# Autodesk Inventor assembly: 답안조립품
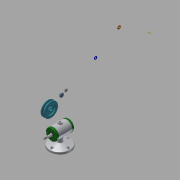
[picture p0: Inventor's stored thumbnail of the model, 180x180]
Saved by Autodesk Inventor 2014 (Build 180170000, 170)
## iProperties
Created: 2018-12
Part Number: 답안조립품
Document SubType Name: Assembly
Designer: kh
Author: kh
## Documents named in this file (15)
- C:\Users\kh\Desktop\481207V1013\답안조립품.iam
- C:\Users\kh\Desktop\481207V1013\본체.ipt
- C:\Users\kh\Desktop\481207V1013\V벨트풀리.ipt
- C:\Users\kh\Desktop\481207V1013\고무캡.ipt
- C:\Users\kh\Desktop\481207V1013\너트 M8.ipt
- 너트 M8.ipt
- C:\Users\kh\Desktop\481207V1013\뒤커버.ipt
- C:\Users\kh\Desktop\481207V1013\베어링 15 x 32 x 9.ipt
- C:\Users\kh\Desktop\481207V1013\볼트 M4 x 12.ipt
- C:\Users\kh\Desktop\481207V1013\스프링와셔 8.ipt
- C:\Users\kh\Desktop\481207V1013\앞커버.ipt
- C:\Users\kh\Desktop\481207V1013\오일 실 15 25 7.ipt
- C:\Users\kh\Desktop\481207V1013\와셔 8x17.ipt
- C:\Users\kh\Desktop\481207V1013\축.ipt
- C:\Users\kh\Desktop\481207V1013\키 3 x 3 x 12.ipt
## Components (2 placed, 2 different names)
1. V벨트풀리:1
2. 고무캡:1
